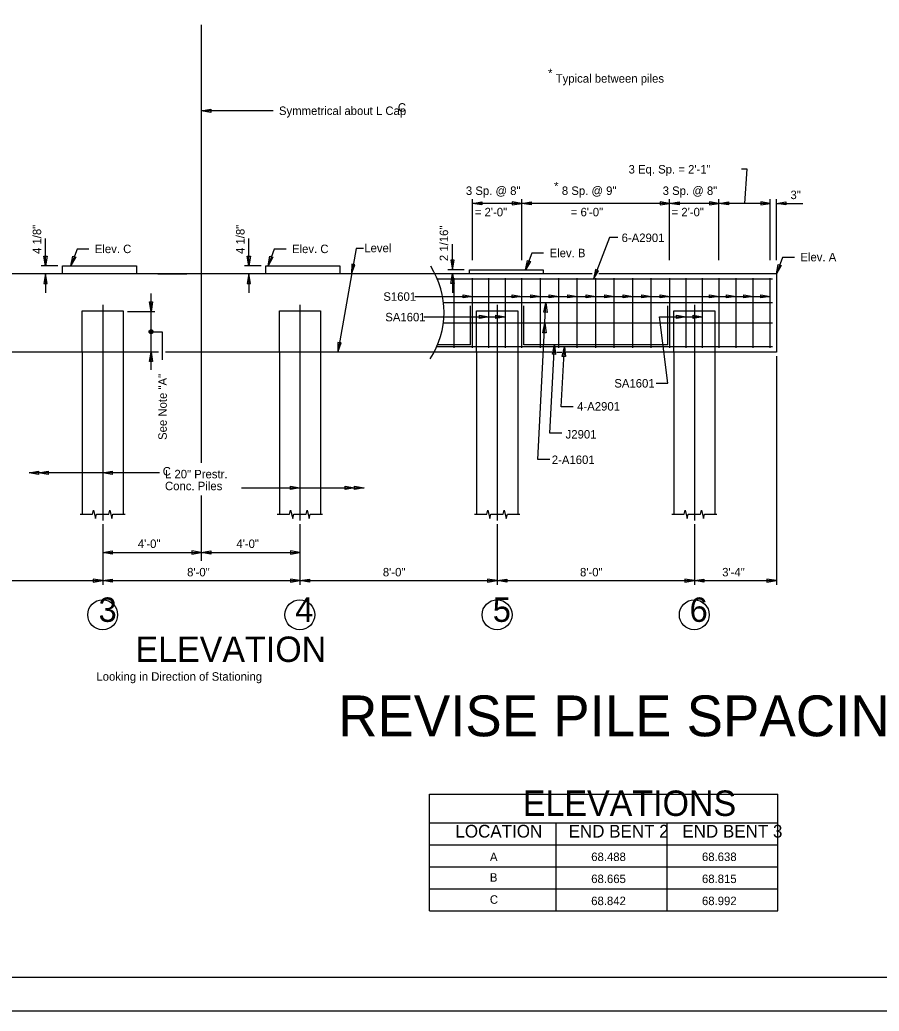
# Model space of a CAD drawing. Extents: x 437 to 537, y 571 to 720.
# Drawn here: x 463.88 to 498.74, y 654.41 to 694.6 of the extents above; entities that cross this region are included whole.
import ezdxf

# ---------------------------------------------------------------- set-up
doc = ezdxf.new("R2010")
doc.units = 0
for name, color, linetype in [('BR_AUTO DIMENSION', 7, 'Continuous'), ('BR_BORDER LINES', 7, 'Continuous'), ('BR_CENTER LINES', 7, 'Continuous'), ('BR_CONCRETE', 7, 'Continuous'), ('BR_PRESTRESSED BEAM', 7, 'Continuous'), ('BR_REBAR', 7, 'Continuous'), ('BR_TABLE LINES', 7, 'Continuous'), ('BR_TEXT', 7, 'Continuous'), ('Default', 7, 'Continuous'), ('RD_SHT_IplotShp', 7, 'Continuous')]:
    doc.layers.add(name, color=color, linetype=linetype)

msp = doc.modelspace()

# ---------------------------------------------------------------- linework, layer by layer
at = {"layer": 'BR_AUTO DIMENSION'}
for p, q in [((471.237, 690.909), (471.624, 690.974)), ((474.147, 690.909), (471.237, 690.909)), ((471.624, 690.844), (471.237, 690.909)), ((471.624, 690.974), (471.624, 690.844)), ((493.152, 688.551), (493.364, 688.551)), ((493.364, 688.551), (493.279, 687.155)), ((482.237, 685.204), (482.237, 687.327)), ((482.237, 684.851), (482.237, 687.327)), ((484.237, 685.204), (484.237, 687.327)), ((484.237, 684.851), (484.237, 687.327)), ((490.237, 685.204), (490.237, 687.327)), ((490.237, 684.851), (490.237, 687.327)), ((492.237, 685.204), (492.237, 687.327)), ((492.237, 684.851), (492.237, 687.327)), ((494.321, 684.851), (494.321, 687.327)), ((494.571, 684.851), (494.571, 687.327)), ((482.237, 687.155), (482.624, 687.219)), ((489.862, 687.155), (482.237, 687.155)), ((482.624, 687.09), (482.237, 687.155)), ((482.624, 687.219), (482.624, 687.09)), ((483.851, 687.219), (483.85, 687.09)), ((483.85, 687.09), (484.237, 687.155)), ((484.237, 687.155), (483.851, 687.219)), ((484.237, 687.155), (484.624, 687.219)), ((484.624, 687.09), (484.237, 687.155)), ((484.624, 687.219), (484.624, 687.09)), ((489.851, 687.219), (489.85, 687.09)), ((489.85, 687.09), (490.237, 687.155)), ((490.237, 687.155), (489.851, 687.219)), ((492.237, 687.155), (489.862, 687.155)), ((490.237, 687.155), (490.624, 687.219)), ((490.624, 687.09), (490.237, 687.155)), ((490.624, 687.219), (490.624, 687.09)), ((491.851, 687.219), (491.85, 687.09)), ((491.85, 687.09), (492.237, 687.155)), ((492.237, 687.155), (491.851, 687.219)), ((492.237, 687.155), (492.624, 687.219)), ((494.321, 687.155), (492.237, 687.155)), ((492.624, 687.09), (492.237, 687.155)), ((492.624, 687.219), (492.624, 687.09)), ((494.321, 687.155), (493.934, 687.219)), ((493.934, 687.219), (493.934, 687.09)), ((493.934, 687.09), (494.321, 687.155)), ((494.571, 687.155), (494.957, 687.219)), ((494.571, 687.155), (495.637, 687.155)), ((494.957, 687.09), (494.571, 687.155)), ((494.957, 687.219), (494.957, 687.09)), ((464.92, 684.627), (464.92, 685.728)), ((473.17, 684.627), (473.17, 685.728)), ((487.793, 685.766), (487.153, 684.085)), ((488.135, 685.766), (487.793, 685.766)), ((466.198, 685.299), (465.947, 684.627)), ((466.677, 685.299), (466.198, 685.299)), ((474.198, 685.299), (473.947, 684.627)), ((474.677, 685.299), (474.198, 685.299)), ((477.518, 685.322), (476.778, 681.127)), ((477.816, 685.322), (477.518, 685.322)), ((481.428, 684.46), (481.428, 685.506)), ((464.855, 685.013), (464.984, 685.014)), ((464.92, 684.627), (464.855, 685.013)), ((464.984, 685.014), (464.92, 684.627)), ((465.947, 684.627), (466.021, 685.012)), ((466.142, 684.967), (465.947, 684.627)), ((466.021, 685.012), (466.142, 684.967)), ((473.105, 685.013), (473.234, 685.014)), ((473.17, 684.627), (473.105, 685.013)), ((473.234, 685.014), (473.17, 684.627)), ((473.947, 684.627), (474.021, 685.012)), ((474.142, 684.967), (473.947, 684.627)), ((474.021, 685.012), (474.142, 684.967)), ((481.493, 684.847), (481.364, 684.847)), ((481.364, 684.847), (481.428, 684.46)), ((481.428, 684.46), (481.493, 684.847)), ((484.647, 685.132), (484.396, 684.46)), ((484.396, 684.46), (484.471, 684.845)), ((484.471, 684.845), (484.591, 684.8)), ((485.126, 685.132), (484.647, 685.132)), ((494.822, 684.966), (494.571, 684.293)), ((495.301, 684.966), (494.822, 684.966)), ((465.415, 684.627), (464.745, 684.627)), ((473.665, 684.627), (472.995, 684.627)), ((477.34, 684.685), (477.337, 684.293)), ((477.337, 684.293), (477.467, 684.663)), ((477.467, 684.663), (477.34, 684.685)), ((481.907, 684.46), (481.238, 684.46)), ((484.591, 684.8), (484.396, 684.46)), ((487.23, 684.469), (487.153, 684.085)), ((487.351, 684.423), (487.23, 684.469)), ((494.571, 684.293), (494.645, 684.678)), ((494.766, 684.633), (494.571, 684.293)), ((494.645, 684.678), (494.766, 684.633)), ((464.92, 684.293), (464.855, 683.907)), ((464.92, 684.293), (464.92, 683.523)), ((464.984, 683.906), (464.92, 684.293)), ((469.472, 684.293), (470.648, 684.293)), ((473.003, 684.293), (471.827, 684.293)), ((473.17, 684.293), (473.105, 683.907)), ((473.17, 684.293), (473.17, 683.523)), ((473.234, 683.906), (473.17, 684.293)), ((481.364, 683.906), (481.428, 684.293)), ((481.428, 684.293), (481.493, 683.907)), ((481.428, 684.293), (481.428, 683.523)), ((487.153, 684.085), (487.351, 684.423)), ((464.855, 683.907), (464.984, 683.906)), ((473.105, 683.907), (473.234, 683.906)), ((481.493, 683.907), (481.364, 683.906)), ((469.199, 680.403), (469.199, 683.502)), ((479.906, 683.385), (494.321, 683.385)), ((481.855, 683.321), (481.855, 683.45)), ((481.855, 683.45), (482.242, 683.385)), ((482.242, 683.385), (481.855, 683.321)), ((483.855, 683.321), (483.855, 683.45)), ((483.855, 683.45), (484.242, 683.385)), ((484.242, 683.385), (483.855, 683.321)), ((484.605, 683.321), (484.605, 683.45)), ((484.605, 683.45), (484.992, 683.385)), ((484.992, 683.385), (484.605, 683.321)), ((485.355, 683.321), (485.355, 683.45)), ((485.355, 683.45), (485.742, 683.385)), ((485.742, 683.385), (485.355, 683.321)), ((486.105, 683.321), (486.105, 683.45)), ((486.105, 683.45), (486.492, 683.385)), ((486.492, 683.385), (486.105, 683.321)), ((486.855, 683.321), (486.855, 683.45)), ((486.855, 683.45), (487.242, 683.385)), ((487.242, 683.385), (486.855, 683.321)), ((487.605, 683.321), (487.605, 683.45)), ((487.605, 683.45), (487.992, 683.385)), ((487.992, 683.385), (487.605, 683.321)), ((488.355, 683.321), (488.355, 683.45)), ((488.355, 683.45), (488.742, 683.385)), ((488.742, 683.385), (488.355, 683.321)), ((489.105, 683.321), (489.105, 683.45)), ((489.105, 683.45), (489.492, 683.385)), ((489.492, 683.385), (489.105, 683.321)), ((489.855, 683.321), (489.855, 683.45)), ((489.855, 683.45), (490.242, 683.385)), ((490.242, 683.385), (489.855, 683.321)), ((491.855, 683.321), (491.855, 683.45)), ((491.855, 683.45), (492.242, 683.385)), ((492.242, 683.385), (491.855, 683.321)), ((492.548, 683.321), (492.548, 683.45)), ((492.548, 683.45), (492.935, 683.385)), ((492.935, 683.385), (492.548, 683.321)), ((493.241, 683.321), (493.241, 683.45)), ((493.241, 683.45), (493.628, 683.385)), ((493.628, 683.385), (493.241, 683.321)), ((493.934, 683.321), (493.934, 683.45)), ((493.934, 683.45), (494.321, 683.385)), ((494.321, 683.385), (493.934, 683.321)), ((469.199, 682.771), (469.135, 683.158)), ((469.135, 683.158), (469.264, 683.158)), ((469.264, 683.158), (469.199, 682.771)), ((484.892, 676.767), (485.22, 683.127)), ((485.136, 682.744), (485.22, 683.127)), ((485.22, 683.127), (485.265, 682.737)), ((468.242, 682.771), (469.357, 682.771)), ((480.272, 682.552), (483.575, 682.552)), ((482.522, 682.488), (482.522, 682.617)), ((482.522, 682.617), (482.908, 682.552)), ((482.908, 682.552), (482.522, 682.488)), ((483.188, 682.488), (483.188, 682.617)), ((483.188, 682.617), (483.575, 682.552)), ((483.575, 682.552), (483.188, 682.488)), ((485.265, 682.737), (485.136, 682.744)), ((489.824, 682.552), (491.575, 682.552)), ((490.158, 679.871), (489.824, 682.552)), ((490.522, 682.488), (490.522, 682.617)), ((490.522, 682.617), (490.909, 682.552)), ((490.909, 682.552), (490.522, 682.488)), ((491.188, 682.488), (491.188, 682.617)), ((491.188, 682.617), (491.575, 682.552)), ((491.575, 682.552), (491.188, 682.488)), ((485.093, 681.91), (485.177, 682.293)), ((485.177, 682.293), (485.222, 681.904)), ((469.177, 681.952), (469.645, 681.952)), ((469.645, 681.952), (469.645, 680.817)), ((485.222, 681.904), (485.093, 681.91)), ((476.782, 681.519), (476.778, 681.127)), ((476.778, 681.127), (476.909, 681.496)), ((476.909, 681.496), (476.782, 681.519)), ((485.379, 677.836), (485.567, 681.418)), ((485.483, 681.035), (485.567, 681.418)), ((485.567, 681.418), (485.612, 681.029)), ((485.838, 678.906), (485.966, 681.335)), ((485.882, 680.952), (485.966, 681.335)), ((485.966, 681.335), (486.01, 680.945)), ((469.135, 680.74), (469.199, 681.127)), ((469.199, 681.127), (469.264, 680.74)), ((485.612, 681.029), (485.483, 681.035)), ((486.01, 680.945), (485.882, 680.952)), ((494.571, 680.955), (494.571, 671.689)), ((469.264, 680.74), (469.135, 680.74)), ((489.685, 679.871), (490.158, 679.871)), ((486.325, 678.906), (485.838, 678.906)), ((485.866, 677.836), (485.379, 677.836)), ((485.379, 676.767), (484.892, 676.767)), ((464.253, 676.229), (464.64, 676.293)), ((469.541, 676.229), (464.253, 676.229)), ((464.64, 676.164), (464.253, 676.229)), ((464.64, 676.293), (464.64, 676.164)), ((464.64, 676.229), (465.026, 676.293)), ((465.026, 676.164), (464.64, 676.229)), ((465.026, 676.293), (465.026, 676.164)), ((467.242, 676.229), (467.629, 676.293)), ((467.629, 676.164), (467.242, 676.229)), ((467.629, 676.293), (467.629, 676.164)), ((472.865, 675.623), (477.844, 675.623)), ((474.855, 675.559), (474.855, 675.688)), ((474.855, 675.688), (475.242, 675.623)), ((475.242, 675.623), (474.855, 675.559)), ((477.07, 675.559), (477.07, 675.688)), ((477.07, 675.688), (477.457, 675.623)), ((477.457, 675.623), (477.07, 675.559)), ((477.457, 675.559), (477.457, 675.688)), ((477.457, 675.688), (477.844, 675.623)), ((477.844, 675.623), (477.457, 675.559)), ((467.242, 674.146), (467.242, 671.689)), ((475.242, 674.146), (475.242, 671.689)), ((483.242, 674.146), (483.242, 671.689)), ((491.242, 674.146), (491.242, 671.689)), ((467.242, 673.002), (467.629, 673.067)), ((467.242, 673.002), (475.242, 673.002)), ((467.629, 672.938), (467.242, 673.002)), ((467.629, 673.067), (467.629, 672.938)), ((470.851, 673.067), (470.85, 672.938)), ((470.85, 672.938), (471.237, 673.002)), ((471.237, 673.002), (470.851, 673.067)), ((471.237, 673.002), (471.624, 673.067)), ((471.624, 672.938), (471.237, 673.002)), ((471.624, 673.067), (471.624, 672.938)), ((475.242, 673.002), (474.855, 673.067)), ((474.855, 673.067), (474.855, 672.938)), ((474.855, 672.938), (475.242, 673.002)), ((491.242, 672.377), (491.242, 671.689)), ((459.237, 671.861), (469.571, 671.861)), ((467.242, 671.861), (466.855, 671.925)), ((466.855, 671.925), (466.855, 671.796)), ((466.855, 671.796), (467.242, 671.861)), ((467.242, 671.861), (467.629, 671.925)), ((467.629, 671.796), (467.242, 671.861)), ((467.629, 671.925), (467.629, 671.796)), ((469.571, 671.861), (478.737, 671.861)), ((475.242, 671.861), (474.855, 671.925)), ((474.855, 671.925), (474.855, 671.796)), ((474.855, 671.796), (475.242, 671.861)), ((475.242, 671.861), (475.629, 671.925)), ((475.629, 671.796), (475.242, 671.861)), ((475.629, 671.925), (475.629, 671.796)), ((478.737, 671.861), (485.612, 671.861)), ((479.779, 671.861), (491.237, 671.861)), ((483.242, 671.861), (482.855, 671.925)), ((482.855, 671.925), (482.855, 671.796)), ((482.855, 671.796), (483.242, 671.861)), ((483.242, 671.861), (483.629, 671.925)), ((483.629, 671.796), (483.242, 671.861)), ((483.629, 671.925), (483.629, 671.796)), ((491.242, 671.861), (490.855, 671.925)), ((490.855, 671.925), (490.855, 671.796)), ((490.855, 671.796), (491.242, 671.861)), ((491.237, 671.861), (494.571, 671.861)), ((491.242, 671.861), (491.629, 671.925)), ((491.629, 671.796), (491.242, 671.861)), ((491.629, 671.925), (491.629, 671.796)), ((494.571, 671.861), (494.184, 671.925)), ((494.184, 671.925), (494.184, 671.796)), ((494.184, 671.796), (494.571, 671.861)), ((484.231, 662.044), (486.385, 662.044))]:
    msp.add_line(p, q, dxfattribs=at)
for centre in [(467.237, 670.476), (475.237, 670.476), (483.237, 670.476), (491.237, 670.476)]:
    msp.add_circle(centre, 0.606, dxfattribs=at)
at = {"layer": 'BR_BORDER LINES'}
for p, q in [((480.492, 658.469), (480.492, 663.209)), ((480.492, 663.209), (494.625, 663.209)), ((494.625, 658.469), (494.625, 663.209)), ((480.492, 662.044), (494.625, 662.044)), ((480.492, 658.469), (494.625, 658.469)), ((442.23, 655.783), (534.814, 655.78)), ((442.231, 655.78), (534.814, 655.78))]:
    msp.add_line(p, q, dxfattribs=at)
at = {"layer": 'BR_CENTER LINES'}
for p, q in [((471.237, 694.389), (471.237, 676.634)), ((467.242, 683.043), (467.242, 681.127)), ((475.242, 683.043), (475.242, 681.127)), ((483.242, 683.043), (483.242, 681.127)), ((491.242, 683.043), (491.242, 681.127)), ((467.242, 681.127), (467.242, 674.293)), ((475.242, 681.127), (475.242, 674.293)), ((483.242, 681.127), (483.242, 674.293)), ((491.242, 681.127), (491.242, 674.293)), ((471.237, 675.306), (471.237, 672.66))]:
    msp.add_line(p, q, dxfattribs=at)
at = {"layer": 'BR_CONCRETE'}
for p, q in [((465.612, 684.293), (465.612, 684.627)), ((465.612, 684.627), (468.612, 684.627)), ((468.612, 684.627), (468.612, 684.293)), ((473.862, 684.293), (473.862, 684.627)), ((473.862, 684.627), (476.862, 684.627)), ((476.862, 684.627), (476.862, 684.293)), ((482.112, 684.293), (482.112, 684.46)), ((482.112, 684.46), (485.112, 684.46)), ((485.112, 684.46), (485.112, 684.293)), ((468.612, 684.293), (460.362, 684.293)), ((473.862, 684.293), (468.612, 684.293)), ((482.112, 684.293), (473.862, 684.293)), ((487.1, 684.293), (482.112, 684.293)), ((494.571, 684.293), (487.367, 684.293)), ((494.571, 684.293), (494.571, 681.127)), ((468.254, 681.127), (458.079, 681.127)), ((469.5, 681.127), (468.254, 681.127)), ((485.458, 681.127), (469.79, 681.127)), ((485.649, 681.127), (485.868, 681.127)), ((494.571, 681.127), (486.037, 681.127))]:
    msp.add_line(p, q, dxfattribs=at)
at = {"layer": 'BR_PRESTRESSED BEAM'}
for p, q in [((466.409, 681.127), (466.409, 682.793)), ((466.409, 682.793), (468.075, 682.793)), ((468.075, 682.793), (468.075, 681.127)), ((474.409, 681.127), (474.409, 682.793)), ((474.409, 682.793), (476.075, 682.793)), ((476.075, 682.793), (476.075, 681.127)), ((482.409, 681.127), (482.409, 682.793)), ((482.409, 682.793), (484.075, 682.793)), ((484.075, 682.793), (484.075, 681.127)), ((490.409, 681.127), (490.409, 682.793)), ((490.409, 682.793), (492.075, 682.793)), ((492.075, 682.793), (492.075, 681.127)), ((466.409, 681.127), (466.409, 674.551)), ((468.075, 681.127), (468.075, 674.551)), ((474.409, 681.127), (474.409, 674.551)), ((476.075, 681.127), (476.075, 674.551)), ((482.409, 681.127), (482.409, 674.551)), ((484.075, 681.127), (484.075, 674.551)), ((490.409, 681.127), (490.409, 674.551)), ((492.075, 681.127), (492.075, 674.551))]:
    msp.add_line(p, q, dxfattribs=at)
at = {"layer": 'BR_REBAR'}
for p, q in [((494.407, 684.085), (480.817, 684.085)), ((481.492, 681.293), (481.492, 684.127)), ((482.242, 681.293), (482.242, 684.127)), ((482.908, 681.293), (482.908, 684.127)), ((483.575, 681.293), (483.575, 684.127)), ((484.242, 681.293), (484.242, 684.127)), ((484.242, 681.293), (484.242, 684.127)), ((484.992, 681.293), (484.992, 684.127)), ((485.742, 681.293), (485.742, 684.127)), ((486.492, 681.293), (486.492, 684.127)), ((487.242, 681.293), (487.242, 684.127)), ((487.992, 681.293), (487.992, 684.127)), ((488.742, 681.293), (488.742, 684.127)), ((489.492, 681.293), (489.492, 684.127)), ((490.242, 681.293), (490.242, 684.127)), ((490.909, 681.293), (490.909, 684.127)), ((491.575, 681.293), (491.575, 684.127)), ((492.242, 681.293), (492.242, 684.127)), ((492.242, 681.293), (492.242, 684.127)), ((492.935, 681.293), (492.935, 684.127)), ((493.628, 681.293), (493.628, 684.127)), ((494.321, 681.293), (494.321, 684.127)), ((494.407, 683.127), (481.064, 683.127)), ((482.159, 681.418), (482.159, 683.002)), ((484.325, 681.418), (484.325, 683.002)), ((490.159, 681.418), (490.159, 683.002)), ((494.407, 682.293), (481.056, 682.293)), ((494.407, 681.335), (480.787, 681.335)), ((482.159, 681.418), (480.823, 681.418)), ((490.159, 681.418), (484.325, 681.418)), ((492.242, 681.293), (492.242, 681.293))]:
    msp.add_line(p, q, dxfattribs=at)
at = {"layer": 'BR_TABLE LINES'}
for p, q in [((485.639, 658.469), (485.639, 662.044)), ((490.133, 658.469), (490.133, 662.044)), ((480.492, 661.15), (494.625, 661.15)), ((480.492, 660.257), (494.625, 660.257)), ((480.492, 659.363), (494.625, 659.363))]:
    msp.add_line(p, q, dxfattribs=at)
for points in [[(466.321, 674.551), (466.821, 674.551), (466.862, 674.718), (466.946, 674.385), (466.987, 674.551), (467.237, 674.551)], [(467.237, 674.551), (467.487, 674.551), (467.529, 674.718), (467.612, 674.385), (467.654, 674.551), (468.154, 674.551)], [(474.321, 674.551), (474.821, 674.551), (474.862, 674.718), (474.946, 674.385), (474.987, 674.551), (475.237, 674.551)], [(475.237, 674.551), (475.487, 674.551), (475.529, 674.718), (475.612, 674.385), (475.654, 674.551), (476.154, 674.551)], [(482.321, 674.551), (482.821, 674.551), (482.862, 674.718), (482.946, 674.385), (482.987, 674.551), (483.237, 674.551)], [(483.237, 674.551), (483.487, 674.551), (483.529, 674.718), (483.612, 674.385), (483.654, 674.551), (484.154, 674.551)], [(490.321, 674.551), (490.821, 674.551), (490.862, 674.718), (490.946, 674.385), (490.987, 674.551), (491.237, 674.551)], [(491.237, 674.551), (491.487, 674.551), (491.529, 674.718), (491.612, 674.385), (491.654, 674.551), (492.154, 674.551)]]:
    msp.add_lwpolyline(points, dxfattribs=at)
msp.add_arc((477.603, 682.745), 3.482, 327.0628, 32.2544, dxfattribs=at)
at = {"layer": 'Default'}
for radius in [0.0767, 0.0503, 0.0228]:
    msp.add_circle((469.199, 681.952), radius, dxfattribs=at)
at = {"layer": 'RD_SHT_IplotShp'}
msp.add_lwpolyline([(437.19, 714.906), (536.19, 714.906), (536.19, 654.406), (437.19, 654.406)], close=True, dxfattribs=at)

# ---------------------------------------------------------------- texts
at = {"layer": 'BR_AUTO DIMENSION'}
for s, height, p in [('*', 0.344, (485.305, 692.265)), ('Typical between piles', 0.34375, (485.616, 692.047)), ('3 Sp. @ 8"', 0.3438, (481.972, 687.496)), ('8 Sp. @ 9"', 0.3438, (485.865, 687.496)), ('3 Sp. @ 8"', 0.3438, (489.955, 687.496)), ('= 2\'-0"', 0.3438, (482.333, 686.63)), ('= 6\'-0"', 0.3438, (486.226, 686.63)), ('= 2\'-0"', 0.3438, (490.316, 686.63))]:
    msp.add_text(s, height=height, dxfattribs=at).set_placement(p)
at = {"layer": 'BR_REBAR'}
msp.add_text('REVISE PILE SPACING', height=1.6543, dxfattribs=at).set_placement((476.787, 665.55))
at = {"layer": 'BR_TEXT'}
for s, height, rotation, p in [('Symmetrical about L Cap', 0.34375, 360, (474.388, 690.737)), ('4 1/8"', 0.3437, 90, (464.743, 685.103)), ('4 1/8"', 0.3437, 90, (472.993, 685.103)), ('2 1/16"', 0.3437, 90, (481.252, 684.813)), ('6-A2901', 0.3437, 360, (488.289, 685.587)), ('See Note "A"', 0.34375, 90, (469.838, 677.563)), ('3\'-4"', 0.3438, 360, (492.368, 672.032)), ('ELEVATIONS', 1.0311, 360, (484.28, 662.321)), ('LOCATION', 0.5155, 360, (481.546, 661.444)), ('END BENT 2', 0.5155, 360, (486.138, 661.444)), ('END BENT 3', 0.5155, 360, (490.752, 661.444)), ('A', 0.344, 360, (482.948, 660.492)), ('68.488', 0.3437, 360, (487.056, 660.492)), ('68.638', 0.3437, 360, (491.549, 660.492)), ('B', 0.344, 360, (482.945, 659.656)), ('68.665', 0.3437, 360, (487.056, 659.599)), ('68.815', 0.3437, 360, (491.549, 659.599)), ('C', 0.344, 360, (482.945, 658.76)), ('68.842', 0.3437, 360, (487.056, 658.705)), ('68.992', 0.3437, 360, (491.549, 658.705))]:
    msp.add_text(s, height=height, rotation=rotation, dxfattribs=at).set_placement(p)
for s, height, p in [('C', 0.344, (479.211, 690.871)), ('3 Eq. Sp. = 2\'-1"', 0.34375, (488.571, 688.365)), ('*', 0.344, (485.549, 687.683)), ('3"', 0.3438, (495.139, 687.327)), ('Elev. C', 0.3438, (466.918, 685.138)), ('Elev. C', 0.3438, (474.918, 685.138)), ('Level', 0.3437, (477.849, 685.174)), ('Elev. B', 0.3438, (485.367, 684.971)), ('Elev. A', 0.3438, (495.542, 684.805)), ('S1601', 0.3437, (478.624, 683.205)), ('SA1601', 0.3437, (478.702, 682.372)), ('SA1601', 0.3438, (487.993, 679.688)), ('4-A2901', 0.3438, (486.485, 678.753)), ('J2901', 0.3438, (486.018, 677.62)), ('2-A1601', 0.3438, (485.457, 676.588)), ('C', 0.344, (469.673, 676.122)), ('L 20" Prestr. ', 0.34375, (469.765, 676.008)), ('Conc. Piles', 0.34375, (469.765, 675.526)), ('4\'-0"', 0.3437, (468.665, 673.184)), ('4\'-0"', 0.3437, (472.661, 673.184)), ('8\'-0"', 0.3437, (470.663, 672.032)), ('8\'-0"', 0.3437, (478.603, 672.032)), ('8\'-0"', 0.3437, (486.603, 672.032)), ('3', 0.989, (467.07, 670.188)), ('4', 0.989, (475.047, 670.188)), ('5', 0.989, (483.062, 670.188)), ('6', 0.989, (491.047, 670.188)), ('ELEVATION', 1.0313, (468.567, 668.563)), ('Looking in Direction of Stationing', 0.34375, (466.983, 667.803))]:
    msp.add_text(s, height=height, dxfattribs=at).set_placement(p)

doc.saveas('drawing.dxf')
